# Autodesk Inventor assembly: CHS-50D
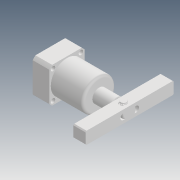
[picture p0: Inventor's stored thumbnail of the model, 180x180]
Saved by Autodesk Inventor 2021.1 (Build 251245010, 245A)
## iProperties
Created: 2019-04
Part Number: CHS-50D
Description: STEP AP203
Document SubType Name: Assembly
Designer: user
Title: chs-50d_asm.STEP
Revision Number: ÈÎºÎ
Sending System: SolidWorks 2017
Preprocessor: SwSTEP 2.0
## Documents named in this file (6)
- D:\Vault_2016\Projekty\Clamptek\Hydraulic\CHS\CHS-50\Inventor\CHS-50D\CHS-50D.iam
- D:\Vault_2016\Projekty\Clamptek\Hydraulic\CHS\CHS-50\Inventor\CHS-50D\CHS-50BT.ipt
- D:\Vault_2016\Projekty\Clamptek\Hydraulic\CHS\CHS-50\Inventor\CHS-50D\CHS-50DHSG.ipt
- D:\Vault_2016\Projekty\Clamptek\Hydraulic\CHS\CHS-50\Inventor\CHS-50D\CHS-50DYB.ipt
- D:\Vault_2016\Projekty\Clamptek\Hydraulic\CHS\CHS-50\Inventor\CHS-50D\ÖáÓÃµ²È¦.ipt
- D:\Vault_2016\Projekty\Clamptek\Hydraulic\CHS\CHS-50\Inventor\CHS-50D\Ïú.ipt
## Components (6 placed, 6 different names)
1. CHS-50BT_1
2. CHS-50DHSG_2
3. CHS-50DYB_3
4. ÖáÓÃµ²È¦_4
5. Ïú_5
6. ÖáÓÃµ²È¦_6
